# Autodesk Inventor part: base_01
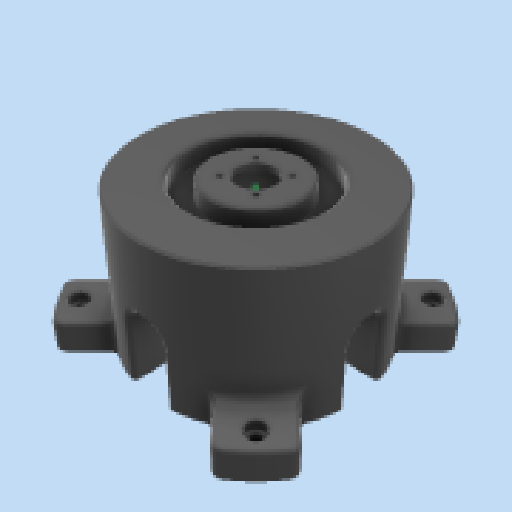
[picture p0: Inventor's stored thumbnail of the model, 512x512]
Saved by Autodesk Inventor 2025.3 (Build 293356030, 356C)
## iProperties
Created: 2025-11
Part Number: base_01
Material: Generico
Document SubType Name: Modeling
Designer: R5800u
Density: 1 g/cm^3
Appearance: Liscia - Nero
Author: R5800u
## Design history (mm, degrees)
node "Piano di lavoro1"
sketch "Schizzo1"
  geometry: L1 (-30, -30)-(30, -30); L2 (30, -30)-(30, 30); L3 (30, 30)-(-30, 30); L4 (-30, 30)-(-30, -30); L5 (-30, -30)-(30, 30); L6 (30, -30)-(-30, 30); L7 (-21.15, -21.15)-(21.15, -21.15); L8 (21.15, -21.15)-(21.15, 21.15); L9 (21.15, 21.15)-(-21.15, 21.15); L10 (-21.15, 21.15)-(-21.15, -21.15); L11 (-21.15, -21.15)-(21.15, 21.15); L12 (21.15, -21.15)-(-21.15, 21.15); C1 r 60 at (0, 0); 1 further point
  constraints: 24 end point, 4 midpoint, 4 parallel, 2 horizontal, 2 perpendicular, 1 centre point, 1 coincident
  dimensions: "d0" = 60 distance of L3.end L2.end; "d1" = 60 distance of L2.end L1.end; "d2" = 42.3 distance of L9.end L8.end; "d3" = 42.3 distance of L8.end L7.end; "d6" = 120 diameter of C1
node "Piano di lavoro2"
extrude "Estrusione1" new body sketch "Schizzo1" stored distance "d4" = 10; taper "d5" = 0 deg
sketch "Schizzo2"
  geometry: L1 (0, 0)-(-60, 0); L2 (-59.161, 10)-(-59.161, 10); L3 (-59.161, 10)-(-59.161, -10); L4 (-59.161, -10)-(-59.161, -10); L5 (-59.161, -10)-(-59.161, 10); C1 r 2.75 at (-50, 0) reference; A1 r 60 centre (0, 0) between (-60, 0) and (-59.161, -10) reference; 4 further points
  constraints: 10 end point, 2 equal length, 2 horizontal, 1 perpendicular, 1 point on circle, 3 other
  dimensions: "d7" = 20 distance of L4.end L2.start
extrude "Estrusione2" join sketch "Schizzo2" distance "d8" = 10; taper "d9" = 0 deg
fillet "Raccordo1" dims "d10" = 5
fillet "Raccordo2" dims "d11" = 3
sketch "Schizzo3"
  geometry: L1 (-46, 2.309)-(-46, -2.309) reference; L2 (-50, 4.619)-(-46, 2.309) reference; L3 (-54, 2.309)-(-50, 4.619) reference; L4 (-54, -2.309)-(-54, 2.309) reference; L5 (-50, -4.619)-(-54, -2.309) reference; L6 (-46, -2.309)-(-50, -4.619) reference; L7 (-45.8, -2.425)-(-45.8, 2.425); L8 (-45.8, 2.425)-(-50, 4.85); L9 (-50, 4.85)-(-54.2, 2.425); L10 (-54.2, 2.425)-(-54.2, -2.425); L11 (-54.2, -2.425)-(-50, -4.85); L12 (-50, -4.85)-(-45.8, -2.425); C1 r 2.5 at (-50, 0) reference; 1 further point
  constraints: 12 end point, 5 other
  dimensions: "d12" = 0.2 distance between parallel lines of L1 L7
extrude "Estrusione3" cut sketch "Schizzo3" distance "d13" = 4; taper "d14" = 0 deg
fillet "Raccordo3" dims "d18" = 3
sketch "Schizzo4"
  geometry: 1 further point
pattern_circular "Serie circolare3" dims "d23" = 360 deg
sketch "Schizzo5"
  geometry: C1 r 60 at (0, 0) reference; C2 r 11 at (0, 0) reference; C3 r 11.5 at (0, 0); C4 r 1.5 at (-9.899, 9.899) reference; C5 r 1.5 at (9.899, 9.899) reference; C6 r 1.5 at (9.899, -9.899) reference; C7 r 1.5 at (-9.899, -9.899) reference; 1 further point
  constraints: 1 centre point
  dimensions: "d25" = 0.5 radial gap between concentric circles of C2 C3
extrude "Estrusione4" join sketch "Schizzo5" distance "d26" = 2; taper "d27" = 0 deg
sketch "Schizzo6"
  geometry: C1 r 60 at (0, 0) reference; C2 r 10 at (0, 0); C3 r 60 at (0, 0) reference; C4 r 1.5 at (-9.899, -9.899) reference; C5 r 1.5 at (9.899, -9.899) reference; C6 r 1.5 at (9.899, 9.899) reference; C7 r 1.5 at (-9.899, 9.899) reference; C8 r 11.5 at (0, 0) reference; 1 further point
  constraints: 1 centre point, 1 coincident
  dimensions: "d29" = 20 diameter of C2
extrude "Estrusione5" join sketch "Schizzo6" distance "d30" = 3; taper "d31" = 0 deg
sketch "Schizzo7"
  geometry: L1 (0, 0)-(0, -45); L2 (9, -40.7)-(-9, -40.7); L3 (-9, -40.7)-(-9, -32.7); L4 (-9, -32.7)-(9, -32.7); L5 (9, -32.7)-(9, -40.7); L6 (-21.15, -40.7)-(21.15, -40.7) reference; 1 further point
  constraints: 10 end point, 2 midpoint, 2 parallel, 1 horizontal, 1 perpendicular, 1 vertical, 1 other
  dimensions: "d33" = 18 distance of L3.end L4.end; "d34" = 8 distance of L2.end L3.end
extrude "Estrusione6" cut sketch "Schizzo7" extent not by distance; stored distance "d35" = 0; taper "d36" = 0 deg
sketch "Schizzo8"
  geometry: 1 further point
sketch "Schizzo9"
  geometry: L1 (-21.15, 21.15)-(21.15, 21.15) reference; L2 (-21.15, -21.15)-(-21.15, 21.15) reference; L3 (21.15, -21.15)-(-21.15, -21.15) reference; L4 (21.15, 21.15)-(21.15, -21.15) reference; L5 (18.15, -18.15)-(-18.15, -18.15); L6 (-18.15, -18.15)-(-18.15, 18.15); L7 (-18.15, 18.15)-(18.15, 18.15); L8 (18.15, 18.15)-(18.15, -18.15); C1 r 11.5 at (0, 0) reference; C2 r 1.5 at (-9.899, -9.899) reference; C3 r 1.5 at (9.899, -9.899) reference; C4 r 1.5 at (9.899, 9.899) reference; C5 r 1.5 at (-9.899, 9.899) reference; 1 further point
  constraints: 8 end point, 3 other
  dimensions: "d37" = 3 distance between parallel lines of L4 L8
extrude "Estrusione7" join sketch "Schizzo9" distance "d38" = 15; taper "d39" = 0 deg
chamfer "Smusso1" distance "d40" = 3; stored, may be unused: second distance "d41" = 2, angle "d42" = 45 deg
node "Piano di lavoro4"
sketch "Schizzo10"
  geometry: C1 r 60 at (0, 0) reference; C2 r 24 at (0, 0); C3 r 35.05 at (0, 0); 1 further point
  constraints: 2 centre point, 2 coincident
  dimensions: "d43" = 48 diameter of C2; "d44" = 70.1 diameter of C3
extrude "Estrusione8" cut sketch "Schizzo10" distance "d45" = 9; taper "d46" = 0 deg
node "Piano di lavoro3"
sketch "Schizzo11"
  geometry: L1 (74.7, 10)-(74.7, -10) reference; L2 (74.7, 0)-(0, 0); L3 (0, -21.15)-(0, 21.15) reference; L4 (0, -8)-(16, -8); L5 (16, -8)-(16, 8); L6 (16, 8)-(0, 8); L7 (0, 8)-(0, -8); 2 further points
  constraints: 10 end point, 2 midpoint, 2 parallel, 2 point on line, 1 horizontal, 1 perpendicular
  dimensions: "d47" = 16 distance of L6.end L5.end; "d48" = 16 distance of L5.end L4.end; "d63" = 2 distance from line of L5 point (14, 0)
hole "Foro1" sketch "Schizzo11" at (14, 0) diameter "d49" = 5.8; stored, may be unused: countersink angle "d53" = 90 deg, drill point angle "d55" = 118 deg; dims "d50" = 6, "d51" = 6.5, "d52" = 3.4, "d54" = 9
pattern_circular "Serie circolare4" dims angle "d57" = 360 deg
sketch "Schizzo12"
  geometry: L1 (31.15, -40)-(11.15, -40); L2 (11.15, -40)-(11.15, 30); L3 (21.15, 40)-(21.15, 40); L4 (31.15, 30)-(31.15, -40); L5 (-38.85, 0)-(81.15, 0) reference; L6 (31.15, -40)-(11.15, 40); L7 (11.15, -40)-(31.15, 40); A1 r 10 centre (21.15, 30) between (31.15, 30) and (21.15, 40); A2 r 10 centre (21.15, 30) between (21.15, 40) and (11.15, 30); 5 further points
  constraints: 12 end point, 4 point on circle, 4 point on line, 4 tangent, 3 midpoint, 2 centre point, 2 parallel, 1 concentric, 1 horizontal, 1 perpendicular
  dimensions: "d59" = 20 distance of L6.end L7.end; "d60" = 80 distance of L1.end L6.end; "d75" = 10 radius of A1
extrude "Estrusione9" cut sketch "Schizzo12" extent not by distance; stored distance "d61" = 0; taper "d62" = 0 deg
sketch "Schizzo13"
  geometry: L1 (10, 59.161)-(10, 21.15) reference; L2 (10, 21.15)-(21.15, 21.15) reference; L3 (21.15, 21.15)-(21.15, -21.15) reference; L4 (21.15, -21.15)-(-21.15, -21.15) reference; L5 (-21.15, -21.15)-(-21.15, 21.15) reference; L6 (-21.15, 21.15)-(-10, 21.15) reference; L7 (-10, 21.15)-(-10, 59.161) reference; A1 r 60 centre (0, 0) between (-10, 59.161) and (10, 59.161) reference; 1 further point
extrude "Estrusione10" join sketch "Schizzo13" distance "d64" = 0.5; taper "d65" = 0 deg
sketch "Schizzo14"
  geometry: L1 (-18.15, 18.15)-(18.15, 18.15) reference; L2 (-18.15, -18.15)-(-18.15, 18.15) reference; L3 (18.15, -18.15)-(-18.15, -18.15) reference; L4 (18.15, 18.15)-(18.15, -18.15) reference; C1 r 18.1 at (0, 0); 1 further point
  constraints: 1 centre point, 1 coincident
  dimensions: "d66" = 36.2 diameter of C1
extrude "Estrusione11" join sketch "Schizzo14" stored distance "d67" = 9; taper "d68" = 0 deg
sketch "Schizzo15"
  geometry: C1 r 24 at (0, 0); C2 r 18.1 at (0, 0) reference; C3 r 30.881 at (0, 0); 1 further point
  constraints: 2 centre point, 2 coincident
extrude "Estrusione12" cut sketch "Schizzo15" stored distance "d69" = 10; taper "d70" = 0 deg
chamfer "Smusso2" distance "d71" = 1; stored, may be unused: second distance "d72" = 2, angle "d73" = 45 deg
pattern_circular "Serie circolare5" dims angle "d77" = 360 deg
sketch "Schizzo16"
  geometry: L1 (38.011, 0)-(0, 0) reference; L2 (0, -20)-(0, 0) reference; L3 (0, -20)-(38.011, -20) reference; A1 r 60 centre (-21.15, -10) between (38.011, -20) and (38.011, 0) reference; 1 further point
extrude "Estrusione13" cut sketch "Schizzo16" distance "d79" = 5; taper "d80" = 0 deg
pattern_circular "Serie circolare6" dims angle "d82" = 360 deg
chamfer "Smusso3" distance "d84" = 4; stored, may be unused: second distance "d85" = 2, angle "d86" = 45 deg
sketch "Schizzo17"
  geometry: L1 (-53.033, 53.033)-(0, 0); L2 (-47.716, 70.343)-(11.314, 11.314); L3 (-70.343, 47.716)-(-11.314, -11.314); C1 r 2.65 at (-53.033, 53.033) reference; C2 r 2.65 at (-53.033, 53.033) reference; A1 r 60 centre (0, 0) between (45, -39.686) and (-45, -39.686) reference; A2 r 60 centre (0, 0) between (45, -39.686) and (-45, -39.686) reference; A3 r 85 centre (0, 0) between (-47.716, 70.343) and (-70.343, 47.716) reference; 3 further points
  constraints: 6 end point, 2 parallel, 2 point on circle
  dimensions: "d87" = 16 distance between parallel lines of L1 L2; "d88" = 16 distance between parallel lines of L1 L3
extrude "Estrusione14" join sketch "Schizzo17" distance "d89" = 15; taper "d90" = 0 deg
fillet "Raccordo7" dims "d91" = 5
sketch "Schizzo18"
  geometry: C1 r 2.65 at (-53.033, -53.033) reference; 2 further points
  constraints: 1 coincident
hole "Foro2" sketch "Schizzo18" at (-53.033, -53.033) diameter "d92" = 5.3; stored, may be unused: countersink angle "d96" = 90 deg, drill point angle "d98" = 118 deg; dims "d93" = 6, "d94" = 10, "d95" = 4.3, "d97" = 8
fillet "Raccordo8" dims "d99" = 5
pattern_circular "Serie circolare7" dims "d101" = 360 deg
fillet "Raccordo9" dims "d103" = 9
fillet "Raccordo10" dims "d104" = 2.4
fillet "Raccordo11" dims "d105" = 2.4
feature "Ղ耀Մ耀Ն耀Ո耀Պ耀Ռ耀Վ耀Ր耀" dims "d0" = 60, "d1" = 60, "d2" = 42.3, "d3" = 42.3, "d4" = 10, "d5" = 0, "d6" = 120, "d7" = 20, "d8" = 10, "d9" = 0, "d10" = 5, "d11" = 3, "d12" = 0.2, "d13" = 4, "d14" = 0, "d18" = 3, "d22" = 60, "d23" = 360 deg, "d25" = 0.5, "d26" = 2, "d27" = 0, "d29" = 20, "d30" = 3, "d31" = 0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
node "Solido1"
node "Riferimento1"
node "Riferimento2"
node "Riferimento3"
node "Riferimento4"
node "Riferimento5"
node "Riferimento6"
node "Riferimento7"
node "Riferimento8"
node "Linea chiusa proiettata1"
node "Linea chiusa proiettata2"
node "Linea chiusa proiettata3"
node "Linea chiusa proiettata4"
node "Riferimento9"
node "Riferimento10"
node "Riferimento11"
node "Riferimento12"
node "Riferimento13"
